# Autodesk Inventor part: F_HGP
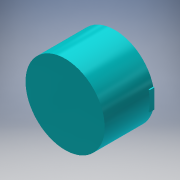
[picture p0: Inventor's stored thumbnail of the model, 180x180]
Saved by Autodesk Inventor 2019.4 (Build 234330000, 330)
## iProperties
Created: 2019-11
Part Number: F_HGP
Material: Generic
Document SubType Name: Modeling
Designer: Willist
Density: 1 g/cm^3
Appearance: F_HGP, F_HGP
Author: Willist
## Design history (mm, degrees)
sketch "F_HGP, F_HGP_135"
  geometry: L1 (-8.712, 2.032)-(8.001, 2.032); L2 (8.001, 2.032)-(8.001, -2.032); L3 (8.001, -2.032)-(-8.712, -2.032); L4 (-8.712, -2.032)-(-8.712, 2.032)
  constraints: 8 end point
extrude "Extrusion1" join sketch "F_HGP, F_HGP_135" distance "d0" = 1; taper "d1" = 0 deg
sketch "Sketch2"
  geometry: L1 (8.001, 2.032)-(-8.712, 2.032) reference; L2 (-8.712, 2.032)-(-8.712, -2.032) reference; L3 (8.001, 2.032)-(-8.712, 2.032); L4 (-8.712, 2.032)-(-8.712, -2.032); L5 (-8.712, -2.032)-(8.001, -2.032); L6 (8.001, -2.032)-(8.001, 2.032); C1 r 8.357 at (-0.356, 0); 1 further point
  constraints: 8 end point, 2 parallel, 1 centre point, 1 horizontal, 1 perpendicular
extrude "Extrusion2" join sketch "Sketch2" distance "d2" = 9.5; taper "d4" = 0 deg; dims "d3" = 1, "d5" = 0
body "Solid1"
